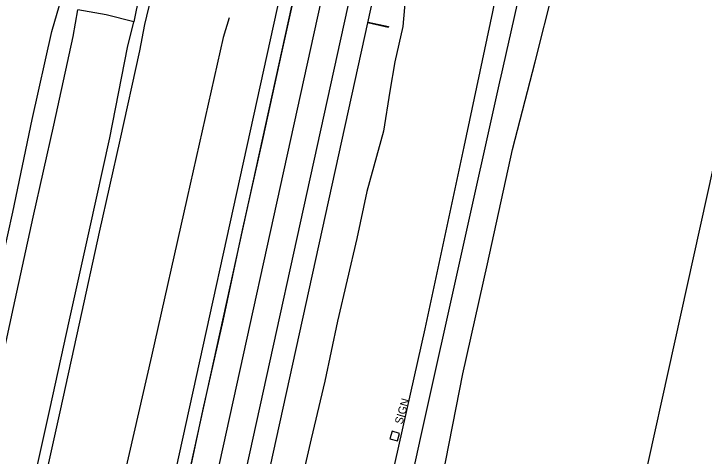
# Model space of a CAD drawing. Extents: x 14105231 to 14123593, y 8636972 to 8671693.
# Drawn here: x 14108503.3 to 14108804.9, y 8642649.6 to 8642842.8 of the extents above; entities that cross this region are included whole.
import ezdxf

# ---------------------------------------------------------------- set-up
doc = ezdxf.new("R2010")
doc.units = 0
for name, color, linetype in [('dsn3DCenterLine', 7, 'Continuous'), ('dsn3DPavementTop', 7, 'Continuous'), ('dsn3DShoulderTop', 7, 'Continuous'), ('dsnSubdrains', 7, 'Continuous'), ('PhoDrainageArrow', 7, 'Continuous'), ('PhoEdgeRoadPaved', 7, 'Continuous'), ('PhoEdgeShoulderPaved', 7, 'Continuous'), ('PhoEdgeShoulderUnpaved', 7, 'Continuous'), ('PhoRailRoadTrack', 7, 'Continuous'), ('PhoRoadPoints', 7, 'Continuous'), ('SurEdgeRoadPaved', 7, 'Continuous'), ('SurEdgeShoulderPaved', 7, 'Continuous')]:
    doc.layers.add(name, color=color, linetype=linetype)

msp = doc.modelspace()

# ---------------------------------------------------------------- linework, layer by layer
at = {"layer": 'dsn3DCenterLine'}
msp.add_lwpolyline([(14108566.82, 8642526.24), (14108653.72, 8642921.81)], dxfattribs=at)
at = {"layer": 'dsn3DPavementTop'}
for points in [[(14108555.1, 8642528.82), (14108642, 8642924.38)], [(14108578.54, 8642523.67), (14108665.44, 8642919.23)]]:
    msp.add_lwpolyline(points, dxfattribs=at)
at = {"layer": 'dsn3DShoulderTop'}
for points in [[(14108549.24, 8642530.11), (14108636.14, 8642925.67)], [(14108549.24, 8642530.11), (14108636.14, 8642925.67)], [(14108588.31, 8642521.52), (14108675.21, 8642917.09)]]:
    msp.add_lwpolyline(points, dxfattribs=at)
at = {"layer": 'dsnSubdrains'}
msp.add_lwpolyline([(14108658, 8642838.79), (14108658.08, 8642839.12), (14108666.96, 8642837.17), (14108666.88, 8642836.84)], close=True, dxfattribs=at)
at = {"layer": 'PhoDrainageArrow'}
for points in [[(14108681.46, 8642872.49), (14108677.76, 8642867.06), (14108674.99, 8642857.26), (14108673.25, 8642837.21), (14108669.73, 8642821.78), (14108667.62, 8642808.96), (14108664.82, 8642791.6), (14108657.52, 8642765.21), (14108653.16, 8642744.64), (14108644.7, 8642708.5), (14108639.18, 8642682.3), (14108633.24, 8642657.23), (14108628.35, 8642635.76)], [(14108597.41, 8642841), (14108594.84, 8642832.48), (14108579.07, 8642762.52), (14108563.44, 8642693.32), (14108545.95, 8642617.17), (14108530.27, 8642548.43), (14108515.21, 8642482.09), (14108497.55, 8642400.47), (14108488.07, 8642351.75), (14108473.26, 8642277.23), (14108457.34, 8642200.73), (14108440.04, 8642117.32), (14108426.79, 8642054.91), (14108412.02, 8641986.97), (14108394.39, 8641909.18), (14108382.32, 8641856.94), (14108368.25, 8641792.63)]]:
    msp.add_lwpolyline(points, dxfattribs=at)
at = {"layer": 'PhoEdgeRoadPaved'}
for points in [[(14108655.05, 8642984.44), (14108646.62, 8642946.06), (14108636.79, 8642900.34), (14108629.1, 8642865.95), (14108620.46, 8642826.51), (14108611.99, 8642787.87), (14108603.09, 8642748.23), (14108594.61, 8642708.71), (14108585.96, 8642670.08), (14108577.35, 8642629.76), (14108560.06, 8642551.64), (14108551.22, 8642512.37), (14108542.49, 8642472.15), (14108534.05, 8642433.28), (14108525.43, 8642394.13), (14108517.1, 8642355.82), (14108505.78, 8642304.1)], [(14108408.22, 8642282.74), (14108416.84, 8642322.21), (14108425.36, 8642361.25), (14108434.24, 8642400.66), (14108442.83, 8642439.93), (14108451.29, 8642479.08), (14108459.88, 8642518.37), (14108468.46, 8642557.78), (14108477.03, 8642597.16), (14108485.84, 8642636.18), (14108494.55, 8642675.4), (14108503.19, 8642714.56), (14108511.84, 8642753.93), (14108520.77, 8642794.08), (14108529.32, 8642832.9), (14108531.26, 8642844.56)], [(14108441.37, 8642316.82), (14108449.88, 8642355.78), (14108458.76, 8642395.19), (14108467.37, 8642434.56), (14108475.83, 8642473.7), (14108484.41, 8642512.98), (14108492.99, 8642552.4), (14108501.54, 8642591.69), (14108510.35, 8642630.67), (14108519.06, 8642669.94), (14108527.71, 8642709.13), (14108536.36, 8642748.47), (14108545.29, 8642788.62), (14108552.94, 8642828.02), (14108555.82, 8642839.24)]]:
    msp.add_lwpolyline(points, dxfattribs=at)
at = {"layer": 'PhoEdgeShoulderPaved'}
for points in [[(14108399.8, 8642284.57), (14108408.41, 8642324.04), (14108416.94, 8642363.1), (14108425.82, 8642402.52), (14108434.4, 8642441.75), (14108442.86, 8642480.9), (14108451.45, 8642520.19), (14108460.03, 8642559.6), (14108468.6, 8642599.01), (14108477.43, 8642638.05), (14108485.61, 8642677.31), (14108494.04, 8642716.62), (14108502.86, 8642756.12), (14108511.33, 8642796.67), (14108519.94, 8642835.08), (14108523.26, 8642846.52)], [(14108445.83, 8642315.82), (14108454.33, 8642354.75), (14108463.21, 8642394.16), (14108471.83, 8642433.57), (14108480.29, 8642472.71), (14108488.87, 8642511.98), (14108497.45, 8642551.41), (14108506, 8642590.67), (14108514.8, 8642629.62), (14108523.52, 8642668.91), (14108532.17, 8642708.11), (14108540.81, 8642747.45), (14108549.74, 8642787.6), (14108558.33, 8642826.6), (14108560.51, 8642838.14)]]:
    msp.add_lwpolyline(points, dxfattribs=at)
at = {"layer": 'PhoEdgeShoulderUnpaved'}
for points in [[(14108722.07, 8642881.37), (14108718.82, 8642875.51), (14108712.49, 8642843.7), (14108699.96, 8642784.66), (14108682.89, 8642705.25), (14108668.17, 8642639.76), (14108657.31, 8642590.87), (14108649.66, 8642552.9), (14108640.16, 8642510), (14108631.49, 8642473.58), (14108622.5, 8642432.73), (14108612.7, 8642386.99), (14108602.16, 8642342.35), (14108590.77, 8642288.4)], [(14108617.54, 8642312.29), (14108622.46, 8642336.79), (14108628.47, 8642363.46), (14108637.38, 8642400.69), (14108648.56, 8642452.4), (14108658.87, 8642495.96), (14108668.54, 8642540.94), (14108679.16, 8642586.18), (14108690.58, 8642640.21), (14108699.56, 8642685.57), (14108710.29, 8642733.61), (14108721.19, 8642783.45), (14108731.03, 8642821.74), (14108739.12, 8642853.73), (14108743.11, 8642868.32), (14108741.86, 8642877.29)]]:
    msp.add_lwpolyline(points, dxfattribs=at)
at = {"layer": 'PhoRailRoadTrack'}
for points in [[(14108111.89, 8639603.32), (14108223.02, 8640108.8), (14108321.24, 8640556.85), (14108389.01, 8640865.95), (14108466.39, 8641217.04), (14108579.44, 8641730.84), (14108667.4, 8642132.59), (14108747.16, 8642495.71), (14108823.03, 8642839), (14108872.22, 8643064.53), (14108931.84, 8643335.45), (14108991.64, 8643609.03), (14109051.05, 8643877.56), (14109162.83, 8644387.73), (14109185, 8644489.59)], [(14108716, 8642814.31), (14108728.13, 8642868.69), (14108735.61, 8642903.92), (14108746.88, 8642954.83), (14108761.35, 8643020.45)], [(14108351.22, 8641154.7), (14108363.42, 8641212.85), (14108409.23, 8641418.25), (14108465.28, 8641674.75), (14108494.94, 8641810.65), (14108577.95, 8642187.96), (14108616.81, 8642364.08), (14108681.32, 8642658.55), (14108715.92, 8642814.39)]]:
    msp.add_lwpolyline(points, dxfattribs=at)
at = {"layer": 'PhoRoadPoints'}
msp.add_lwpolyline([(14108671.42, 8642657.87), (14108671.42, 8642657.87), (14108671.89, 8642659.51), (14108668.6, 8642660.47), (14108667.65, 8642657.18), (14108670.94, 8642656.22), (14108671.41, 8642657.87)], dxfattribs=at)
at = {"layer": 'SurEdgeRoadPaved'}
msp.add_lwpolyline([(14108590.94, 8642983.09), (14108586.9, 8642963.63), (14108585.69, 8642963.9), (14108579.72, 8642935.87), (14108580.83, 8642935.59), (14108576.37, 8642916.18), (14108572.36, 8642916.94), (14108562.53, 8642872.43), (14108555.82, 8642839.24), (14108543.71, 8642842.34), (14108531.26, 8642844.56)], dxfattribs=at)
at = {"layer": 'SurEdgeShoulderPaved'}
msp.add_lwpolyline([(14108560.51, 8642838.14), (14108570.57, 8642879.98), (14108577.94, 8642915.57), (14108588, 8642963.71), (14108588, 8642963.73), (14108592.17, 8642982.51), (14108601.43, 8643029.06), (14108611.53, 8643075.66), (14108615.55, 8643095.95)], dxfattribs=at)

# ---------------------------------------------------------------- texts
at = {"layer": 'PhoRoadPoints'}
msp.add_text('SIGN', height=3.499, rotation=73.7433, dxfattribs=at).set_placement((14108673.02, 8642663.24))

doc.saveas('drawing.dxf')
